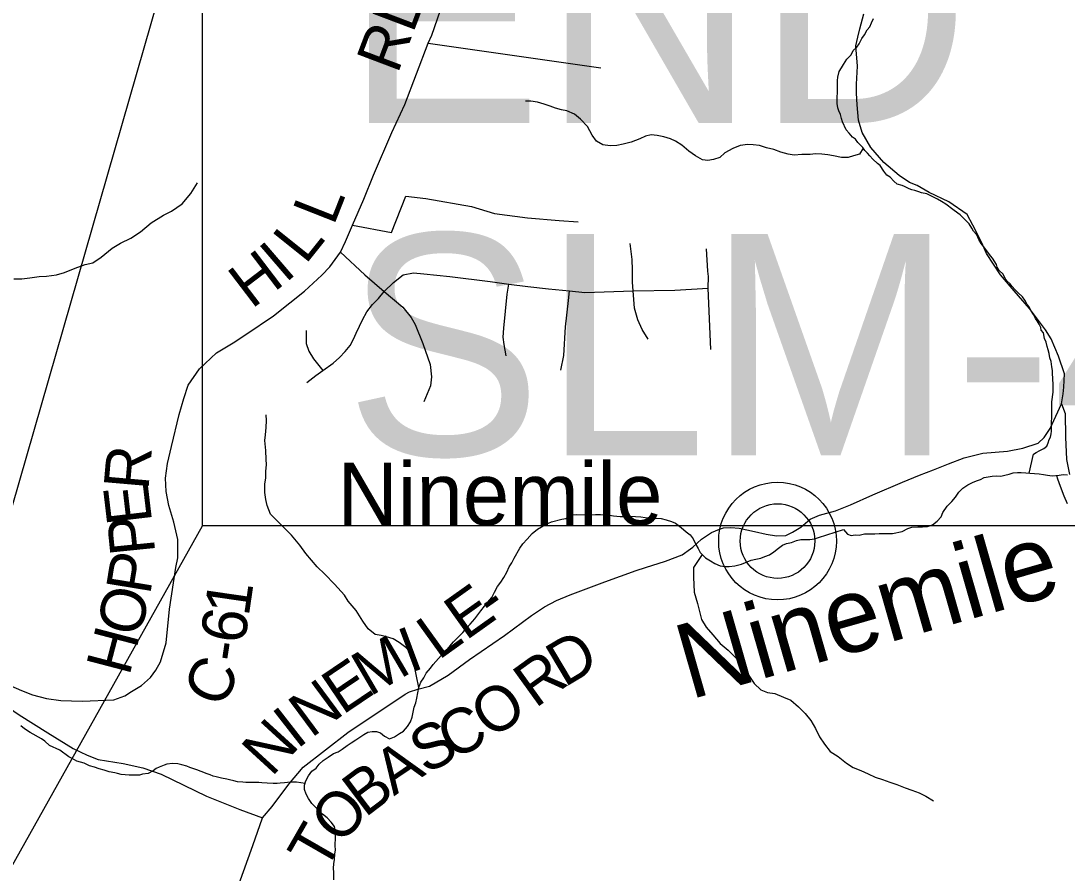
# Model space of a CAD drawing. Extents: x 0 to 34, y 0 to 22.
# Drawn here: x 5.605 to 6.267, y 14.403 to 14.941 of the extents above; entities that cross this region are included whole.
import ezdxf

# ---------------------------------------------------------------- set-up
doc = ezdxf.new("R2010")
doc.units = 0
for name, color, linetype in [('Default', 7, 'Continuous'), ('GM_X_County_Road', 7, 'Continuous'), ('GM_X_County_Road_Text', 7, 'Continuous'), ('GM_X_Minor_River', 7, 'Continuous'), ('GM_X_Minor_River_Text', 7, 'Continuous'), ('GM_X_Township_Road', 7, 'Continuous'), ('GM_X_Unincorporated', 7, 'Continuous'), ('GM_X_Unincorporated_Location', 7, 'Continuous'), ('GM_X_Unincorporated_Text', 7, 'Continuous'), ('SH_Text', 7, 'Continuous')]:
    doc.layers.add(name, color=color, linetype=linetype)

msp = doc.modelspace()

# ---------------------------------------------------------------- linework, layer by layer
at = {"layer": 'Default'}
msp.add_lwpolyline([(5.72003, 15.05333), (7.10043, 15.05333), (7.10043, 14.62233), (5.72003, 14.62233)], close=True, dxfattribs=at)
at = {"layer": 'GM_X_County_Road'}
for points in [[(5.59897, 14.52141), (5.60575, 14.51826), (5.61273, 14.51561), (5.62155, 14.51336), (5.63068, 14.51204), (5.64397, 14.51158), (5.66413, 14.51256), (5.67101, 14.51508), (5.67523, 14.51766), (5.68154, 14.52155), (5.68724, 14.52655), (5.69058, 14.53129), (5.69364, 14.53643), (5.69712, 14.5484), (5.69934, 14.56983), (5.70324, 14.59598), (5.70449, 14.60224), (5.70449, 14.61379), (5.70199, 14.62478), (5.69893, 14.63522), (5.69726, 14.64412), (5.69684, 14.65247), (5.69809, 14.66179), (5.7006, 14.6725), (5.70533, 14.69268), (5.70825, 14.70284), (5.71111, 14.71129), (5.71815, 14.7216), (5.72898, 14.73164), (5.73955, 14.73807), (5.74743, 14.74322), (5.76493, 14.75503), (5.77535, 14.76336), (5.7846, 14.77077), (5.79562, 14.78081), (5.80066, 14.78602), (5.80742, 14.79527), (5.81047, 14.80197), (5.81495, 14.81232), (5.82203, 14.82871), (5.82823, 14.84397), (5.83978, 14.8709), (5.84793, 14.88859), (5.86282, 14.92737), (5.86514, 14.9325), (5.87443, 14.95948)], [(6.263, 14.69939), (6.26404, 14.70573), (6.26452, 14.70992), (6.26492, 14.71845), (6.26122, 14.72954), (6.25642, 14.74062), (6.25293, 14.7462), (6.24278, 14.75971), (6.23315, 14.77092), (6.22444, 14.78098), (6.21562, 14.79446), (6.21256, 14.8016), (6.20707, 14.8123), (6.2035, 14.81914), (6.19187, 14.82716), (6.17944, 14.83297), (6.17189, 14.83739), (6.16701, 14.83925), (6.16038, 14.84366), (6.15074, 14.85192), (6.14248, 14.86144), (6.13714, 14.87097), (6.13468, 14.87875), (6.13388, 14.8884), (6.13342, 14.89572), (6.13354, 14.90153), (6.134, 14.91281), (6.13295, 14.92571), (6.13429, 14.93111), (6.13563, 14.93651), (6.13818, 14.94581)], [(6.02847, 14.60785), (6.03008, 14.60901), (6.03556, 14.61407), (6.04189, 14.61818), (6.04681, 14.62022), (6.04943, 14.62114), (6.05404, 14.6213), (6.05929, 14.62099), (6.06908, 14.61889), (6.07639, 14.61719), (6.08288, 14.6161), (6.08883, 14.61632), (6.09303, 14.6183), (6.09835, 14.62151), (6.10419, 14.6266), (6.11008, 14.62906), (6.12029, 14.63184), (6.12968, 14.63567), (6.14379, 14.64196), (6.16251, 14.65008), (6.17322, 14.65451), (6.18209, 14.65786), (6.1915, 14.66165), (6.20156, 14.66533), (6.21335, 14.66836), (6.22898, 14.66963), (6.23867, 14.67139), (6.2483, 14.67453), (6.25216, 14.67819), (6.25587, 14.68381), (6.263, 14.69939)], [(5.74307, 14.39586), (5.75187, 14.4205), (5.75808, 14.43784), (5.7642, 14.44515), (5.77476, 14.45923), (5.78378, 14.47001), (5.81201, 14.49186), (5.84816, 14.51601), (5.85104, 14.51747), (5.85621, 14.51921), (5.86367, 14.52113), (5.87534, 14.528), (5.88891, 14.53793), (5.91097, 14.55314), (5.92812, 14.56581), (5.93628, 14.57112), (5.94385, 14.57523), (5.95247, 14.57878), (5.97432, 14.58703), (5.99413, 14.59411), (6.00012, 14.59602), (6.01273, 14.60007), (6.02323, 14.60409), (6.02847, 14.60785)], [(5.54031, 14.54464), (5.55242, 14.53676), (5.56802, 14.52819), (5.57559, 14.52219), (5.58993, 14.51276), (5.60428, 14.50303), (5.62246, 14.49154), (5.63847, 14.48181), (5.64722, 14.47748), (5.65419, 14.47483), (5.67001, 14.47228), (5.68249, 14.46943), (5.69399, 14.4654), (5.72259, 14.45159), (5.74363, 14.44316), (5.75808, 14.43784)]]:
    msp.add_lwpolyline(points, dxfattribs=at)
at = {"layer": 'GM_X_Minor_River'}
for points in [[(6.1215, 14.90025), (6.12137, 14.90387), (6.12159, 14.90595), (6.1226, 14.90955), (6.12397, 14.91181), (6.12534, 14.91387), (6.1273, 14.91726), (6.13, 14.92007), (6.13138, 14.9227), (6.1337, 14.92494), (6.13506, 14.92701), (6.13683, 14.9304), (6.13858, 14.93265), (6.14015, 14.93586), (6.1419, 14.93773), (6.14289, 14.94018), (6.14427, 14.94301)], [(6.2426, 14.65576), (6.24533, 14.66763), (6.24706, 14.66874), (6.24936, 14.67004), (6.25185, 14.67132), (6.25378, 14.67281), (6.25457, 14.67489), (6.25518, 14.67697), (6.25615, 14.67847), (6.25657, 14.68056), (6.25679, 14.68227), (6.25662, 14.68379), (6.25681, 14.69501), (6.25691, 14.70071), (6.25777, 14.70678), (6.25766, 14.71134), (6.25754, 14.71572), (6.2574, 14.71839), (6.25724, 14.72048), (6.2569, 14.72277), (6.25674, 14.72448), (6.25639, 14.7262), (6.25566, 14.72849), (6.25514, 14.73136), (6.25461, 14.73365), (6.25389, 14.73575), (6.25336, 14.73842), (6.25226, 14.74072), (6.25156, 14.74435), (6.25026, 14.74608), (6.24991, 14.7478), (6.24899, 14.74991), (6.24769, 14.75183), (6.24658, 14.75337), (6.24529, 14.75587), (6.24381, 14.75817), (6.24252, 14.76067), (6.24122, 14.76221), (6.23974, 14.76509), (6.23845, 14.76702), (6.23545, 14.76992), (6.23395, 14.77128), (6.23172, 14.77379), (6.2306, 14.77533), (6.22873, 14.77707), (6.22742, 14.77862), (6.22614, 14.78149), (6.22371, 14.78381), (6.22241, 14.78593), (6.22187, 14.78746), (6.21947, 14.79149), (6.21816, 14.79304), (6.21574, 14.79612), (6.21388, 14.79863), (6.21221, 14.80075), (6.21073, 14.80325), (6.20945, 14.80631), (6.2074, 14.80863), (6.20629, 14.81055), (6.20463, 14.81324), (6.20313, 14.81479), (6.19902, 14.81885), (6.19752, 14.82002), (6.19432, 14.82217), (6.18982, 14.82567), (6.18718, 14.82742), (6.18474, 14.8288), (6.18247, 14.82979), (6.1804, 14.83097), (6.17795, 14.83215), (6.17454, 14.83278), (6.17284, 14.83338), (6.17038, 14.83418), (6.16849, 14.83479), (6.16679, 14.83539), (6.16377, 14.83677), (6.16226, 14.83737), (6.15924, 14.83837), (6.15698, 14.84012), (6.15475, 14.84263), (6.15268, 14.844), (6.15082, 14.8465), (6.14841, 14.84997), (6.14672, 14.85133), (6.14372, 14.85404), (6.14186, 14.85617), (6.14036, 14.8579), (6.13868, 14.85964), (6.13738, 14.86138), (6.1344, 14.86466), (6.13272, 14.86678), (6.13084, 14.86796), (6.12879, 14.87046), (6.12693, 14.87259), (6.12454, 14.87757), (6.12401, 14.87986), (6.12329, 14.88235), (6.12238, 14.88465), (6.12165, 14.88656), (6.12131, 14.88923), (6.1215, 14.90025)], [(6.13762, 14.86106), (6.13541, 14.85723), (6.13159, 14.85616), (6.12815, 14.85507), (6.12397, 14.85515), (6.11886, 14.85619), (6.11544, 14.85682), (6.11165, 14.85726), (6.10747, 14.85734), (6.10423, 14.85701), (6.09891, 14.85692), (6.09415, 14.85662), (6.09036, 14.85726), (6.08563, 14.85848), (6.08128, 14.86008), (6.07655, 14.8613), (6.0722, 14.86271), (6.06822, 14.86316), (6.0648, 14.86341), (6.05985, 14.86273), (6.05525, 14.86091), (6.05027, 14.85815), (6.04698, 14.85516), (6.04316, 14.8539), (6.03954, 14.8532), (6.03612, 14.85364), (6.03179, 14.85619), (6.02747, 14.85912), (6.02297, 14.863), (6.01903, 14.86554), (6.01582, 14.86692), (6.01166, 14.86814), (6.00749, 14.86897), (6.00369, 14.86942), (6.00007, 14.86853), (5.99662, 14.86688), (5.99107, 14.86489), (5.98591, 14.86346), (5.98191, 14.86277), (5.97772, 14.86246), (5.97317, 14.86311), (5.96922, 14.86546), (5.96643, 14.86931), (5.96348, 14.87468), (5.959, 14.87933), (5.95525, 14.88243), (5.95034, 14.88461), (5.94693, 14.88524), (5.94315, 14.88626), (5.93975, 14.88746), (5.93616, 14.88885), (5.93181, 14.89007), (5.92764, 14.89071), (5.92421, 14.89077)], [(5.60084, 14.77847), (5.60597, 14.77856), (5.61092, 14.77903), (5.61682, 14.77986), (5.62157, 14.78014), (5.62786, 14.78097), (5.63282, 14.78239), (5.63972, 14.78529), (5.64602, 14.78744), (5.65079, 14.78867), (5.65599, 14.79218), (5.66313, 14.79774), (5.66832, 14.80105), (5.67484, 14.80415), (5.681, 14.80821), (5.68775, 14.81377), (5.69545, 14.81875), (5.70043, 14.82112), (5.70717, 14.82592), (5.71281, 14.83246), (5.71693, 14.83903)], [(5.85686, 14.52026), (5.85238, 14.54177), (5.84864, 14.54545), (5.84433, 14.54876), (5.84056, 14.55092), (5.8364, 14.55232), (5.833, 14.55315), (5.8292, 14.55378), (5.82489, 14.55728), (5.82136, 14.5621), (5.81729, 14.56882), (5.81226, 14.57481), (5.80985, 14.57865), (5.80351, 14.58561), (5.79734, 14.5918), (5.79266, 14.59645), (5.78893, 14.6007), (5.78539, 14.60495), (5.78168, 14.61015), (5.77628, 14.61652), (5.77067, 14.62213), (5.76637, 14.62639), (5.76319, 14.62987), (5.761, 14.63523), (5.76012, 14.63905), (5.75943, 14.64343), (5.75952, 14.64895), (5.76015, 14.65255), (5.76022, 14.65673), (5.76049, 14.6611), (5.76035, 14.66433), (5.76007, 14.67004), (5.7596, 14.67633), (5.75985, 14.67994), (5.76031, 14.68449), (5.76058, 14.68905), (5.76045, 14.69248)], [(6.15629, 14.6175), (6.16239, 14.61886), (6.16585, 14.62067), (6.16833, 14.62156), (6.17213, 14.62184), (6.17516, 14.62176), (6.17839, 14.62206), (6.18145, 14.62311), (6.18454, 14.62532), (6.18707, 14.6281), (6.18809, 14.63073), (6.19084, 14.63484), (6.19376, 14.63781), (6.19611, 14.6406), (6.19808, 14.64359), (6.20061, 14.64618), (6.20389, 14.64838), (6.20677, 14.64982), (6.20926, 14.6509), (6.21175, 14.65178), (6.21424, 14.65286), (6.21671, 14.65336), (6.21918, 14.65368), (6.22204, 14.65398), (6.22468, 14.65372), (6.22716, 14.65442), (6.23002, 14.6551), (6.2325, 14.6558), (6.23516, 14.65611), (6.23763, 14.65604), (6.24047, 14.65597), (6.24311, 14.65571), (6.24595, 14.65545), (6.24897, 14.65518), (6.25162, 14.65492), (6.25407, 14.65447), (6.25709, 14.65401), (6.26146, 14.65447), (6.26412, 14.65478), (6.26677, 14.65452)], [(6.25979, 14.65429), (6.26046, 14.65216), (6.2621, 14.64756), (6.26447, 14.64144), (6.26666, 14.63645)], [(5.85686, 14.52026), (5.85809, 14.52365), (5.86005, 14.52645), (5.86145, 14.52926), (5.86419, 14.53242), (5.86595, 14.53485), (5.87102, 14.54041), (5.87395, 14.54357), (5.87648, 14.54635), (5.87883, 14.54914), (5.88155, 14.55192), (5.88467, 14.55507), (5.8872, 14.55786), (5.88935, 14.56027), (5.89228, 14.56362), (5.89405, 14.56623), (5.89601, 14.56865), (5.89836, 14.57163), (5.90051, 14.57423), (5.90305, 14.57721), (5.90464, 14.5804), (5.90664, 14.58415), (5.9086, 14.58675), (5.91057, 14.58974), (5.91236, 14.59312), (5.91397, 14.5965), (5.91554, 14.59893), (5.91714, 14.60193), (5.92071, 14.60829), (5.92249, 14.6111), (5.92541, 14.61406), (5.92853, 14.61759), (5.93182, 14.62036), (5.93432, 14.62181), (5.93683, 14.62327), (5.94066, 14.62488), (5.94733, 14.6266), (5.94981, 14.62711), (5.95347, 14.62929), (5.95632, 14.6296), (5.96559, 14.62935), (5.96844, 14.62947), (5.97166, 14.62957), (5.97639, 14.62926), (5.97998, 14.62879), (5.98414, 14.6283), (5.9866, 14.62823), (5.99021, 14.62852), (5.9938, 14.62823), (5.99721, 14.62814), (5.99985, 14.62769), (6.00325, 14.62722), (6.00666, 14.62732), (6.01006, 14.62704), (6.01326, 14.6262), (6.01646, 14.62517), (6.01908, 14.62415), (6.02261, 14.62139), (6.02576, 14.61865), (6.02837, 14.61668), (6.0302, 14.61416), (6.03181, 14.6107), (6.03345, 14.60799), (6.03471, 14.60549), (6.03804, 14.60217), (6.04121, 14.60019), (6.04401, 14.59859), (6.04738, 14.59717), (6.05059, 14.59671), (6.05305, 14.59665), (6.05666, 14.59712), (6.06086, 14.59815), (6.06431, 14.59958), (6.06699, 14.60065), (6.06985, 14.60134), (6.0729, 14.60202), (6.07558, 14.60309), (6.07845, 14.60415), (6.08115, 14.60598), (6.08424, 14.60837), (6.08675, 14.6102), (6.08924, 14.61128), (6.09229, 14.61196), (6.09554, 14.61321), (6.09821, 14.61371), (6.10124, 14.61382), (6.1039, 14.61375), (6.10694, 14.61424), (6.10943, 14.61512), (6.12528, 14.62003), (6.12767, 14.61711), (6.13011, 14.61629), (6.13259, 14.61679), (6.13504, 14.61654), (6.13848, 14.6174), (6.1417, 14.61732), (6.14511, 14.61742), (6.14777, 14.61754), (6.15023, 14.61747), (6.15326, 14.61758), (6.15629, 14.6175)], [(6.03589, 14.60431), (6.03046, 14.59609), (6.03035, 14.58981), (6.03066, 14.58543), (6.03096, 14.58048), (6.03293, 14.57341), (6.034, 14.56902), (6.03542, 14.56329), (6.03838, 14.55829), (6.04267, 14.55346), (6.04733, 14.54806), (6.05239, 14.54378), (6.058, 14.53817), (6.06192, 14.53373), (6.06506, 14.52854), (6.06876, 14.52277), (6.07307, 14.5187), (6.07722, 14.51711), (6.08177, 14.51646), (6.08725, 14.51408), (6.09197, 14.51228), (6.09684, 14.50802), (6.10095, 14.50376), (6.10468, 14.49932), (6.10745, 14.49433), (6.11002, 14.48915), (6.11317, 14.48453), (6.11671, 14.4799), (6.12178, 14.47658), (6.12723, 14.47249), (6.13136, 14.46975), (6.13627, 14.46777), (6.1408, 14.46579), (6.14533, 14.46362), (6.14986, 14.46221), (6.15459, 14.46041), (6.15893, 14.459), (6.16422, 14.45682), (6.16838, 14.45541), (6.1731, 14.45362), (6.17725, 14.45165), (6.18214, 14.44871)], [(5.80314, 14.39869), (5.80307, 14.40344), (5.80295, 14.40611), (5.80321, 14.40876), (5.80347, 14.41161), (5.80375, 14.41502), (5.8042, 14.41767), (5.80407, 14.42015), (5.80421, 14.42565), (5.80411, 14.42908), (5.80363, 14.43251), (5.80143, 14.43523), (5.79884, 14.43796), (5.79606, 14.44032), (5.79181, 14.44442), (5.78922, 14.44696), (5.78703, 14.45006), (5.78558, 14.45276), (5.78452, 14.45583), (5.78459, 14.45849), (5.78542, 14.46131), (5.78721, 14.4645), (5.78918, 14.4673), (5.79188, 14.46932), (5.79384, 14.47174), (5.79637, 14.47414), (5.79964, 14.47634), (5.80292, 14.47853), (5.80579, 14.4796), (5.80849, 14.48124), (5.81158, 14.48363), (5.81408, 14.48527), (5.81697, 14.48709), (5.81948, 14.48893), (5.82199, 14.49057), (5.82468, 14.49202), (5.82735, 14.49252), (5.83, 14.49245), (5.83263, 14.49163), (5.83523, 14.48947), (5.83841, 14.48786), (5.84147, 14.48911), (5.84455, 14.49112), (5.84725, 14.49276), (5.84959, 14.49555), (5.85157, 14.49854), (5.85259, 14.50155), (5.85324, 14.50458), (5.85389, 14.50779), (5.85491, 14.51062), (5.85555, 14.51345), (5.85686, 14.52026)], [(5.69283, 14.46984), (5.69092, 14.46911), (5.68899, 14.46763), (5.68573, 14.46597), (5.6823, 14.46546), (5.68039, 14.46492), (5.67868, 14.46476), (5.67374, 14.46485), (5.6688, 14.46532), (5.66634, 14.46593), (5.66464, 14.46634), (5.66104, 14.46698), (5.65801, 14.46798), (5.6548, 14.4688), (5.65177, 14.46999), (5.64875, 14.47081), (5.64535, 14.47239), (5.64062, 14.4738), (5.6378, 14.47537), (5.63572, 14.47636), (5.6299, 14.48065), (5.62349, 14.48361), (5.62049, 14.48633), (5.61843, 14.48788), (5.61127, 14.49181), (5.6077, 14.49416), (5.60526, 14.4961)], [(5.78494, 14.45965), (5.77954, 14.46052), (5.77574, 14.4604), (5.77193, 14.46008), (5.76927, 14.45975), (5.76736, 14.45959), (5.7647, 14.45964), (5.7609, 14.4599), (5.75767, 14.45995), (5.75578, 14.46018), (5.74741, 14.46032), (5.74571, 14.46054), (5.74229, 14.4606), (5.74002, 14.46121), (5.73718, 14.46183), (5.73547, 14.46224), (5.73206, 14.46287), (5.73036, 14.46329), (5.72866, 14.46389), (5.72695, 14.4643), (5.72506, 14.46509), (5.72298, 14.4657), (5.71921, 14.46728), (5.71656, 14.46828), (5.71411, 14.46909), (5.71222, 14.46969), (5.71014, 14.47049), (5.70711, 14.4713), (5.70446, 14.47192), (5.70123, 14.47216), (5.69762, 14.47185), (5.69589, 14.47112), (5.69283, 14.46984)]]:
    msp.add_lwpolyline(points, dxfattribs=at)
at = {"layer": 'GM_X_Township_Road'}
msp.add_line((5.86282, 14.92737), (5.97193, 14.91187), dxfattribs=at)
for points in [[(5.81495, 14.81232), (5.83949, 14.80772), (5.84869, 14.83079), (5.86135, 14.82923), (5.89015, 14.8242), (5.90473, 14.81969), (5.92555, 14.81691), (5.9455, 14.81535), (5.95765, 14.81448)], [(5.99223, 14.77079), (5.99193, 14.77641), (5.99193, 14.78417), (5.99158, 14.79076), (5.99051, 14.8007)], [(6.04146, 14.73381), (6.0398, 14.77265), (6.03995, 14.78), (6.03945, 14.78324), (6.03874, 14.79734)], [(5.80742, 14.79527), (5.82268, 14.78095), (5.83501, 14.77042)], [(5.83501, 14.77042), (5.84089, 14.77607), (5.84703, 14.78099), (5.85348, 14.78222), (5.86009, 14.7816), (5.87637, 14.77991), (5.90203, 14.77684), (5.91375, 14.77519), (5.92568, 14.77361), (5.93889, 14.77223), (5.95213, 14.77084), (5.96166, 14.76984), (5.99223, 14.77079), (6.01863, 14.77135), (6.0398, 14.77265)], [(5.91201, 14.72983), (5.91081, 14.73701), (5.91017, 14.74166), (5.91048, 14.74734), (5.91265, 14.7687), (5.91375, 14.77519)], [(5.94666, 14.72071), (5.94856, 14.72998), (5.94947, 14.74822), (5.95151, 14.76477), (5.95213, 14.77084)], [(6.00169, 14.74031), (5.99805, 14.74654), (5.99523, 14.75254), (5.99311, 14.75995), (5.99223, 14.77079)], [(5.78604, 14.71301), (5.79173, 14.71739), (5.7961, 14.7205), (5.80271, 14.72515), (5.80678, 14.72868), (5.81039, 14.7326), (5.81341, 14.73633), (5.8156, 14.74039), (5.81724, 14.74411), (5.81932, 14.74849), (5.82119, 14.75265), (5.82403, 14.75769), (5.82754, 14.76219), (5.83138, 14.76613), (5.83501, 14.77042)], [(5.83501, 14.77042), (5.84676, 14.76054), (5.8519, 14.75393), (5.85452, 14.74964), (5.85932, 14.73751), (5.86404, 14.72442), (5.86485, 14.71647), (5.86424, 14.71094), (5.85993, 14.7008)], [(5.78566, 14.74573), (5.78558, 14.73766), (5.78727, 14.73267), (5.79027, 14.72783), (5.7961, 14.7205)], [(6.263, 14.69939), (6.26526, 14.69337), (6.26556, 14.67842), (6.26623, 14.66433), (6.26816, 14.65477)]]:
    msp.add_lwpolyline(points, dxfattribs=at)
at = {"layer": 'GM_X_Unincorporated'}
for radius in [0.0372, 0.02358]:
    msp.add_circle((6.08355, 14.61277), radius, dxfattribs=at)
at = {"layer": 'GM_X_Unincorporated_Location'}
msp.add_line((6.08355, 14.61277), (6.08355, 14.61277), dxfattribs=at)
at = {"layer": 'SH_Text'}
msp.add_lwpolyline([(5.72003, 15.05333), (5.46527, 14.16778), (5.72003, 14.62233)], close=True, dxfattribs=at)

# ---------------------------------------------------------------- texts
at = {"layer": 'GM_X_County_Road_Text'}
for s, height, rotation, p in [('RD', 0.028409, 69.2734, (5.84338, 14.9074)), ('L', 0.02841, 68.4901, (5.80299, 14.81147)), ('L', 0.02841, 51.36301, (5.78517, 14.78701)), ('I', 0.02841, 40.72011, (5.7724, 14.77533)), ('H', 0.02841, 37.33471, (5.75113, 14.75903)), ('R', 0.02841, 85.03313, (5.68588, 14.64445)), ('E', 0.02841, 96.75005, (5.68836, 14.62488)), ('P', 0.02841, 95.78364, (5.69034, 14.60529)), ('P', 0.02841, 80.69241, (5.68699, 14.57823)), ('E', 0.02841, 35.44352, (5.88653, 14.54953)), ('O', 0.02841, 75.50802, (5.68016, 14.55128)), ('1', 0.02841, 81.73885, (5.74931, 14.56462)), ('-', 0.02841, 35.44785, (5.90384, 14.56185)), ('6', 0.02841, 81.2016, (5.74659, 14.54704)), ('L', 0.02841, 35.72196, (5.8693, 14.53714)), ('H', 0.02841, 75.33467, (5.67381, 14.527)), ('M', 0.02841, 30.34679, (5.8258, 14.51423)), ('I', 0.02841, 20.4793, (5.85124, 14.52925)), ('D', 0.02841, 30.75072, (5.94879, 14.52002)), ('-', 0.02841, 81.35534, (5.74484, 14.53553)), ('R', 0.02841, 35.79493, (5.93042, 14.50673)), ('C', 0.02841, 65.90198, (5.73296, 14.50622)), ('E', 0.02841, 34.04545, (5.8086, 14.50259)), ('N', 0.02841, 36.55151, (5.78878, 14.48789)), ('O', 0.02841, 35.5183, (5.90285, 14.48699)), ('I', 0.02841, 37.97835, (5.77973, 14.48082)), ('C', 0.02841, 26.55981, (5.87782, 14.47406)), ('N', 0.02841, 47.57659, (5.76379, 14.46322)), ('S', 0.02841, 28.31845, (5.86115, 14.46507)), ('A', 0.02841, 34.074, (5.84109, 14.45146)), ('B', 0.02841, 36.9784, (5.82276, 14.43765)), ('O', 0.02841, 48.03066, (5.80711, 14.42004)), ('T', 0.02841, 60.12701, (5.79746, 14.40289))]:
    msp.add_text(s, height=height, rotation=rotation, dxfattribs=at).set_placement(p)
at = {"layer": 'GM_X_Minor_River_Text'}
msp.add_text('Ninemile', height=0.047349, rotation=16.00399, dxfattribs=at).set_placement((6.0281, 14.51246))
at = {"layer": 'GM_X_Unincorporated_Text'}
msp.add_text('Ninemile', height=0.039489, rotation=0.00001, dxfattribs=at).set_placement((5.80545, 14.6229))
at = {"layer": 'SH_Text'}
for s, height, p in [('END PROJECT', 0.1399997, (5.80995, 14.87687)), ('SLM-40.06', 0.14, (5.80995, 14.66687))]:
    msp.add_text(s, height=height, dxfattribs=at).set_placement(p)

doc.saveas('drawing.dxf')
